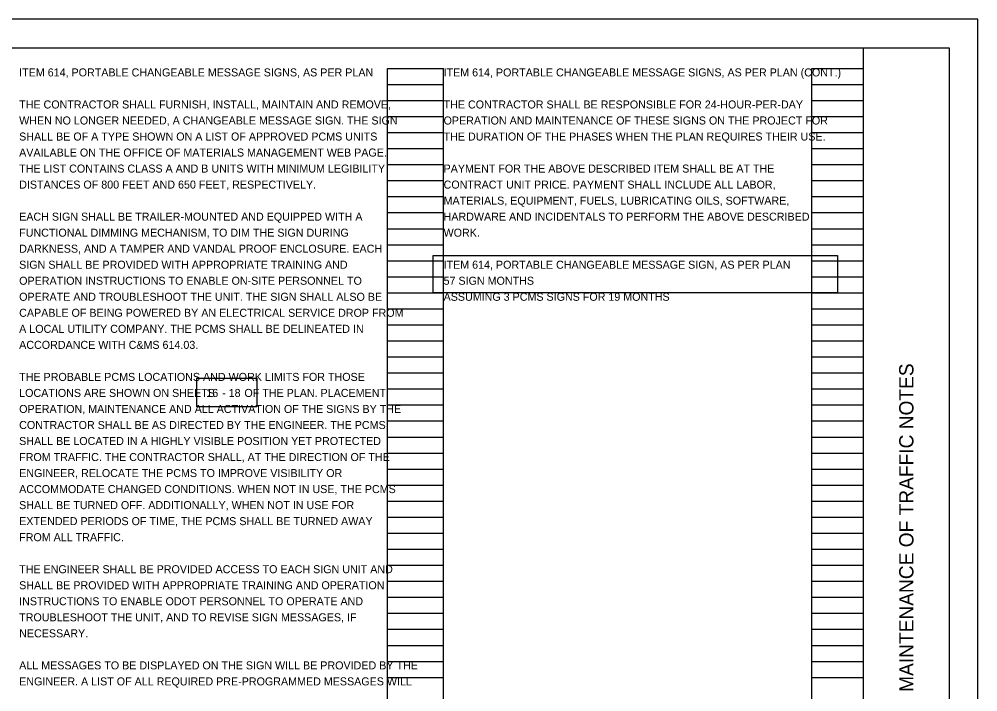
# Model space of a CAD drawing. Extents: x -19 to 34, y 0 to 22.
# Drawn here: x 17.24 to 34, y 10.25 to 22 of the extents above; entities that cross this region are included whole.
import ezdxf

# ---------------------------------------------------------------- set-up
doc = ezdxf.new("R2010")
doc.units = 0
for name, color, linetype in [('SC_Scratch1', 7, 'Continuous'), ('SH_Border', 7, 'Continuous'), ('SH_Cut_Line', 7, 'Continuous'), ('SH_Data', 7, 'Continuous'), ('SH_Text', 7, 'Continuous')]:
    doc.layers.add(name, color=color, linetype=linetype)

msp = doc.modelspace()

# ---------------------------------------------------------------- linework, layer by layer
at = {"layer": 'SC_Scratch1'}
for points in [[(24.476, 17.874), (31.548, 17.874), (31.548, 17.217), (24.476, 17.217)], [(20.348, 15.727), (21.393, 15.727), (21.393, 15.226), (20.348, 15.226)]]:
    msp.add_lwpolyline(points, close=True, dxfattribs=at)
at = {"layer": 'SH_Border'}
msp.add_line((32, 0.5), (32, 21.5), dxfattribs=at)
msp.add_lwpolyline([(1.5, 21.5), (33.5, 21.5), (33.5, 0.5), (1.5, 0.5)], close=True, dxfattribs=at)
at = {"layer": 'SH_Cut_Line'}
msp.add_lwpolyline([(0, 0), (34, 0), (34, 22), (0, 22)], close=True, dxfattribs=at)
at = {"layer": 'SH_Data'}
for p, q in [((23.68, 0.98), (23.68, 21.14)), ((23.68, 21.14), (24.66, 21.14)), ((24.66, 0.98), (24.66, 21.14)), ((31.1, 0.98), (31.1, 21.14)), ((31.1, 21.14), (32, 21.14)), ((32, 0.98), (32, 21.14)), ((23.68, 20.86), (24.66, 20.86)), ((31.1, 20.86), (32, 20.86)), ((23.68, 20.58), (24.66, 20.58)), ((31.1, 20.58), (32, 20.58)), ((23.68, 20.3), (24.66, 20.3)), ((31.1, 20.3), (32, 20.3)), ((23.68, 20.02), (24.66, 20.02)), ((31.1, 20.02), (32, 20.02)), ((23.68, 19.74), (24.66, 19.74)), ((31.1, 19.74), (32, 19.74)), ((23.68, 19.46), (24.66, 19.46)), ((31.1, 19.46), (32, 19.46)), ((23.68, 19.18), (24.66, 19.18)), ((31.1, 19.18), (32, 19.18)), ((23.68, 18.9), (24.66, 18.9)), ((31.1, 18.9), (32, 18.9)), ((23.68, 18.62), (24.66, 18.62)), ((31.1, 18.62), (32, 18.62)), ((23.68, 18.34), (24.66, 18.34)), ((31.1, 18.34), (32, 18.34)), ((23.68, 18.06), (24.66, 18.06)), ((31.1, 18.06), (32, 18.06)), ((23.68, 17.78), (24.66, 17.78)), ((31.1, 17.78), (32, 17.78)), ((23.68, 17.5), (24.66, 17.5)), ((31.1, 17.5), (32, 17.5)), ((23.68, 17.22), (24.66, 17.22)), ((31.1, 17.22), (32, 17.22)), ((23.68, 16.94), (24.66, 16.94)), ((31.1, 16.94), (32, 16.94)), ((23.68, 16.66), (24.66, 16.66)), ((31.1, 16.66), (32, 16.66)), ((23.68, 16.38), (24.66, 16.38)), ((31.1, 16.38), (32, 16.38)), ((23.68, 16.1), (24.66, 16.1)), ((31.1, 16.1), (32, 16.1)), ((23.68, 15.82), (24.66, 15.82)), ((31.1, 15.82), (32, 15.82)), ((23.68, 15.54), (24.66, 15.54)), ((31.1, 15.54), (32, 15.54)), ((23.68, 15.26), (24.66, 15.26)), ((31.1, 15.26), (32, 15.26)), ((23.68, 14.98), (24.66, 14.98)), ((31.1, 14.98), (32, 14.98)), ((23.68, 14.7), (24.66, 14.7)), ((31.1, 14.7), (32, 14.7)), ((23.68, 14.42), (24.66, 14.42)), ((31.1, 14.42), (32, 14.42)), ((23.68, 14.14), (24.66, 14.14)), ((31.1, 14.14), (32, 14.14)), ((23.68, 13.86), (24.66, 13.86)), ((31.1, 13.86), (32, 13.86)), ((23.68, 13.58), (24.66, 13.58)), ((31.1, 13.58), (32, 13.58)), ((23.68, 13.3), (24.66, 13.3)), ((31.1, 13.3), (32, 13.3)), ((23.68, 13.02), (24.66, 13.02)), ((31.1, 13.02), (32, 13.02)), ((23.68, 12.74), (24.66, 12.74)), ((31.1, 12.74), (32, 12.74)), ((23.68, 12.46), (24.66, 12.46)), ((31.1, 12.46), (32, 12.46)), ((23.68, 12.18), (24.66, 12.18)), ((31.1, 12.18), (32, 12.18)), ((23.68, 11.9), (24.66, 11.9)), ((31.1, 11.9), (32, 11.9)), ((23.68, 11.62), (24.66, 11.62)), ((31.1, 11.62), (32, 11.62)), ((23.68, 11.34), (24.66, 11.34)), ((31.1, 11.34), (32, 11.34)), ((23.68, 11.06), (24.66, 11.06)), ((31.1, 11.06), (32, 11.06)), ((23.68, 10.78), (24.66, 10.78)), ((31.1, 10.78), (32, 10.78)), ((23.68, 10.5), (24.66, 10.5)), ((31.1, 10.5), (32, 10.5))]:
    msp.add_line(p, q, dxfattribs=at)

# ---------------------------------------------------------------- texts
msp.add_text('MAINTENANCE OF TRAFFIC NOTES', height=0.25, rotation=90, dxfattribs=at).set_placement((32.875, 10.247))
at = {"layer": 'SH_Text'}
for s, p in [('ITEM 614, PORTABLE CHANGEABLE MESSAGE SIGNS, AS PER PLAN', (17.24, 21)), ('ITEM 614, PORTABLE CHANGEABLE MESSAGE SIGNS, AS PER PLAN (CONT.)', (24.66, 21)), ('THE CONTRACTOR SHALL FURNISH, INSTALL, MAINTAIN AND REMOVE, ', (17.24, 20.44)), ('THE CONTRACTOR SHALL BE RESPONSIBLE FOR 24-HOUR-PER-DAY ', (24.66, 20.44)), ('WHEN NO LONGER NEEDED, A CHANGEABLE MESSAGE SIGN. THE SIGN ', (17.24, 20.16)), ('OPERATION AND MAINTENANCE OF THESE SIGNS ON THE PROJECT FOR ', (24.66, 20.16)), ('SHALL BE OF A TYPE SHOWN ON A LIST OF APPROVED PCMS UNITS ', (17.24, 19.88)), ('THE DURATION OF THE PHASES WHEN THE PLAN REQUIRES THEIR USE. ', (24.66, 19.88)), ('AVAILABLE ON THE OFFICE OF MATERIALS MANAGEMENT WEB PAGE. ', (17.24, 19.6)), ('THE LIST CONTAINS CLASS A AND B UNITS WITH MINIMUM LEGIBILITY ', (17.24, 19.32)), ('PAYMENT FOR THE ABOVE DESCRIBED ITEM SHALL BE AT THE ', (24.66, 19.32)), ('DISTANCES OF 800 FEET AND 650 FEET, RESPECTIVELY.  ', (17.24, 19.04)), ('CONTRACT UNIT PRICE. PAYMENT SHALL INCLUDE ALL LABOR, ', (24.66, 19.04)), ('MATERIALS, EQUIPMENT, FUELS, LUBRICATING OILS, SOFTWARE, ', (24.66, 18.76)), ('EACH SIGN SHALL BE TRAILER-MOUNTED AND EQUIPPED WITH A ', (17.24, 18.48)), ('HARDWARE AND INCIDENTALS TO PERFORM THE ABOVE DESCRIBED ', (24.66, 18.48)), ('FUNCTIONAL DIMMING MECHANISM, TO DIM THE SIGN DURING ', (17.24, 18.2)), ('WORK.  ', (24.66, 18.2)), ('DARKNESS, AND A TAMPER AND VANDAL PROOF ENCLOSURE. EACH ', (17.24, 17.92)), ('SIGN SHALL BE PROVIDED WITH APPROPRIATE TRAINING AND ', (17.24, 17.64)), ('ITEM 614, PORTABLE CHANGEABLE MESSAGE SIGN, AS PER PLAN', (24.66, 17.64)), ('OPERATION INSTRUCTIONS TO ENABLE ON-SITE PERSONNEL TO ', (17.24, 17.36)), ('57 SIGN MONTHS', (24.66, 17.36)), ('OPERATE AND TROUBLESHOOT THE UNIT. THE SIGN SHALL ALSO BE ', (17.24, 17.08)), ('ASSUMING 3 PCMS SIGNS FOR 19 MONTHS              ', (24.66, 17.08)), ('CAPABLE OF BEING POWERED BY AN ELECTRICAL SERVICE DROP FROM ', (17.24, 16.8)), ('A LOCAL UTILITY COMPANY. THE PCMS SHALL BE DELINEATED IN ', (17.24, 16.52)), ('ACCORDANCE WITH C&MS 614.03. ', (17.24, 16.24)), ('THE PROBABLE PCMS LOCATIONS AND WORK LIMITS FOR THOSE ', (17.24, 15.68)), ('LOCATIONS ARE SHOWN ON SHEETS', (17.24, 15.4)), ('16', (20.512, 15.4)), (' - ', (20.736, 15.4)), ('18', (20.903, 15.4)), (' OF THE PLAN. PLACEMENT, ', (21.126, 15.4)), ('OPERATION, MAINTENANCE AND ALL ACTIVATION OF THE SIGNS BY THE ', (17.24, 15.12)), ('CONTRACTOR SHALL BE AS DIRECTED BY THE ENGINEER. THE PCMS ', (17.24, 14.84)), ('SHALL BE LOCATED IN A HIGHLY VISIBLE POSITION YET PROTECTED ', (17.24, 14.56)), ('FROM TRAFFIC. THE CONTRACTOR SHALL, AT THE DIRECTION OF THE ', (17.24, 14.28)), ('ENGINEER, RELOCATE THE PCMS TO IMPROVE VISIBILITY OR ', (17.24, 14)), ('ACCOMMODATE CHANGED CONDITIONS. WHEN NOT IN USE, THE PCMS ', (17.24, 13.72)), ('SHALL BE TURNED OFF. ADDITIONALLY, WHEN NOT IN USE FOR ', (17.24, 13.44)), ('EXTENDED PERIODS OF TIME, THE PCMS SHALL BE TURNED AWAY ', (17.24, 13.16)), ('FROM ALL TRAFFIC.  ', (17.24, 12.88)), ('THE ENGINEER SHALL BE PROVIDED ACCESS TO EACH SIGN UNIT AND ', (17.24, 12.32)), ('SHALL BE PROVIDED WITH APPROPRIATE TRAINING AND OPERATION ', (17.24, 12.04)), ('INSTRUCTIONS TO ENABLE ODOT PERSONNEL TO OPERATE AND ', (17.24, 11.76)), ('TROUBLESHOOT THE UNIT, AND TO REVISE SIGN MESSAGES, IF ', (17.24, 11.48)), ('NECESSARY.', (17.24, 11.2)), ('ALL MESSAGES TO BE DISPLAYED ON THE SIGN WILL BE PROVIDED BY THE ', (17.24, 10.64)), ('ENGINEER. A LIST OF ALL REQUIRED PRE-PROGRAMMED MESSAGES WILL ', (17.24, 10.36))]:
    msp.add_text(s, height=0.14, dxfattribs=at).set_placement(p)

doc.saveas('drawing.dxf')
